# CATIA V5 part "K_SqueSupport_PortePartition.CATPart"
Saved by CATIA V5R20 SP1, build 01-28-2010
Part number: squelette_support_porte_partition
Publications: "Point.1", "Point.2", "Point.3", "Point.4", "Point.5", "Point.6", "Droite.1", "Plan.1", "Droite.2", "Droite.3", "Droite.4", "Droite.5"
Bounding box of the stored display mesh (mm): x -2 to 19, y 0 to 6, z 0 to 200
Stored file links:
  G:\Khaled_CFAO_2011\ST2M\ST2M_GR2\gcausse\Khaled\CAD_ThinkMotion\K_SqueSupport_PortePartition.CATPart
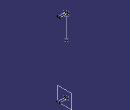
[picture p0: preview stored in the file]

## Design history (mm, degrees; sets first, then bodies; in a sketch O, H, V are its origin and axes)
Set1
  Point1: (-1, 0, 0)
  Point2: (-2, 0, 200)
  Point3: (-2, 6, 200)
  Point4: (-1, 6, 0)
  Point5: (-2, 3, 195)
  Point6: (-2, 3, 135)
  Line1: type PtPt, FirstPoint Point6, SecondPoint Point5
  Plane1: type Offset, RefPlane yz-plane, Offset 0
  Line2: type PtDir, RefPoint Point3, Direction Plane1, Start 0, End 20
  Line3: type Normal, RefPoint Point2, RefSkin Plane1, Start 0, End 20
  Line4: type PtDir, RefPoint Point4, Direction Plane1, Start 0, End 20
  Line5: type PtDir, RefPoint Point1, Direction Plane1, Start 0, End 20
Body1 (main body)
